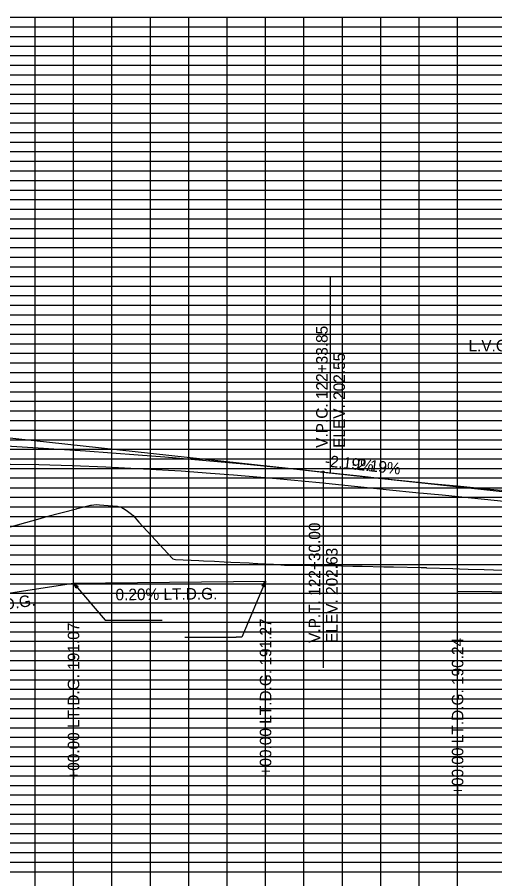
# Model space of a CAD drawing. Extents: x 1451449 to 1456010, y 297581 to 299758.
# Drawn here: x 1453550.4 to 1453799, y 299104.9 to 299553.5 of the extents above; entities that cross this region are included whole.
import ezdxf

# ---------------------------------------------------------------- set-up
doc = ezdxf.new("R2010")
doc.units = 0
for name, color, linetype in [('Existing Profile Grade', 7, 'Continuous'), ('Grid_Major', 7, 'Continuous'), ('Grid_Minor', 7, 'Continuous'), ('PR_Exist Surface', 7, 'Continuous'), ('PR_exist_ground', 7, 'Continuous'), ('PRF_Scratch', 7, 'Continuous'), ('Profile Annotation', 7, 'Continuous'), ('Profile Annotation Line', 7, 'Continuous'), ('Special_Ditch_LT', 7, 'Continuous')]:
    doc.layers.add(name, color=color, linetype=linetype)

msp = doc.modelspace()

# ---------------------------------------------------------------- linework, layer by layer
at = {"layer": 'Existing Profile Grade'}
for points in [[(1453496.53, 299321), (1453514.29, 299320.93), (1453532.09, 299320.86), (1453546.85, 299320.78), (1453561.6, 299320.71), (1453579.05, 299320.08), (1453596.5, 299319.44), (1453616.07, 299318.37), (1453635.64, 299317.31), (1453650.94, 299316.15)], [(1453650.94, 299316.15), (1453663.04, 299315.28)], [(1453663.04, 299315.28), (1453685.36, 299313.25), (1453707.69, 299311.23), (1453725.94, 299309.3), (1453744.18, 299307.37), (1453757.95, 299306.06), (1453771.71, 299304.75), (1453793.64, 299302.54), (1453815.57, 299300.33)]]:
    msp.add_lwpolyline(points, dxfattribs=at)
at = {"layer": 'Grid_Major'}
for p, q in [((1451479.67, 299553.55), (1455979.67, 299553.55)), ((1451479.67, 299553.55), (1455979.67, 299553.55)), ((1453579.67, 298953.55), (1453579.67, 299553.55)), ((1453679.67, 298953.55), (1453679.67, 299553.55)), ((1453779.67, 298953.55), (1453779.67, 299553.55)), ((1451479.67, 299503.55), (1455979.67, 299503.55)), ((1451479.67, 299453.55), (1455979.67, 299453.55)), ((1451479.67, 299403.55), (1455979.67, 299403.55)), ((1451479.67, 299353.55), (1455979.67, 299353.55)), ((1451479.67, 299303.55), (1455979.67, 299303.55)), ((1451479.67, 299253.55), (1455979.67, 299253.55)), ((1451479.67, 299203.55), (1455979.67, 299203.55)), ((1451479.67, 299153.55), (1455979.67, 299153.55))]:
    msp.add_line(p, q, dxfattribs=at)
at = {"layer": 'Grid_Minor'}
for p, q in [((1453559.67, 298953.55), (1453559.67, 299553.55)), ((1453599.67, 298953.55), (1453599.67, 299553.55)), ((1453619.67, 298953.55), (1453619.67, 299553.55)), ((1453639.67, 298953.55), (1453639.67, 299553.55)), ((1453659.67, 298953.55), (1453659.67, 299553.55)), ((1453699.67, 298953.55), (1453699.67, 299553.55)), ((1453719.67, 298953.55), (1453719.67, 299553.55)), ((1453739.67, 298953.55), (1453739.67, 299553.55)), ((1453759.67, 298953.55), (1453759.67, 299553.55)), ((1451479.67, 299548.55), (1455979.67, 299548.55)), ((1451479.67, 299543.55), (1455979.67, 299543.55)), ((1451479.67, 299538.55), (1455979.67, 299538.55)), ((1451479.67, 299533.55), (1455979.67, 299533.55)), ((1451479.67, 299528.55), (1455979.67, 299528.55)), ((1451479.67, 299523.55), (1455979.67, 299523.55)), ((1451479.67, 299518.55), (1455979.67, 299518.55)), ((1451479.67, 299513.55), (1455979.67, 299513.55)), ((1451479.67, 299508.55), (1455979.67, 299508.55)), ((1451479.67, 299498.55), (1455979.67, 299498.55)), ((1451479.67, 299493.55), (1455979.67, 299493.55)), ((1451479.67, 299488.55), (1455979.67, 299488.55)), ((1451479.67, 299483.55), (1455979.67, 299483.55)), ((1451479.67, 299478.55), (1455979.67, 299478.55)), ((1451479.67, 299473.55), (1455979.67, 299473.55)), ((1451479.67, 299468.55), (1455979.67, 299468.55)), ((1451479.67, 299463.55), (1455979.67, 299463.55)), ((1451479.67, 299458.55), (1455979.67, 299458.55)), ((1451479.67, 299448.55), (1455979.67, 299448.55)), ((1451479.67, 299443.55), (1455979.67, 299443.55)), ((1451479.67, 299438.55), (1455979.67, 299438.55)), ((1451479.67, 299433.55), (1455979.67, 299433.55)), ((1451479.67, 299428.55), (1455979.67, 299428.55)), ((1451479.67, 299423.55), (1455979.67, 299423.55)), ((1451479.67, 299418.55), (1455979.67, 299418.55)), ((1451479.67, 299413.55), (1455979.67, 299413.55)), ((1451479.67, 299408.55), (1455979.67, 299408.55)), ((1451479.67, 299398.55), (1455979.67, 299398.55)), ((1451479.67, 299393.55), (1455979.67, 299393.55)), ((1451479.67, 299388.55), (1455979.67, 299388.55)), ((1451479.67, 299383.55), (1455979.67, 299383.55)), ((1451479.67, 299378.55), (1455979.67, 299378.55)), ((1451479.67, 299373.55), (1455979.67, 299373.55)), ((1451479.67, 299368.55), (1455979.67, 299368.55)), ((1451479.67, 299363.55), (1455979.67, 299363.55)), ((1451479.67, 299358.55), (1455979.67, 299358.55)), ((1451479.67, 299348.55), (1455979.67, 299348.55)), ((1451479.67, 299343.55), (1455979.67, 299343.55)), ((1451479.67, 299338.55), (1455979.67, 299338.55)), ((1451479.67, 299333.55), (1455979.67, 299333.55)), ((1451479.67, 299328.55), (1455979.67, 299328.55)), ((1451479.67, 299323.55), (1455979.67, 299323.55)), ((1451479.67, 299318.55), (1455979.67, 299318.55)), ((1451482.2, 299313.64), (1455982.2, 299313.64)), ((1451479.67, 299308.55), (1455979.67, 299308.55)), ((1451479.67, 299298.55), (1455979.67, 299298.55)), ((1451479.67, 299293.55), (1455979.67, 299293.55)), ((1451479.67, 299288.55), (1455979.67, 299288.55)), ((1451479.67, 299283.55), (1455979.67, 299283.55)), ((1451479.67, 299278.55), (1455979.67, 299278.55)), ((1451479.67, 299273.55), (1455979.67, 299273.55)), ((1451479.67, 299268.55), (1455979.67, 299268.55)), ((1451479.67, 299263.55), (1455979.67, 299263.55)), ((1451479.67, 299258.55), (1455979.67, 299258.55)), ((1451479.67, 299248.55), (1455979.67, 299248.55)), ((1451479.67, 299243.55), (1455979.67, 299243.55)), ((1451479.67, 299238.55), (1455979.67, 299238.55)), ((1451479.67, 299233.55), (1455979.67, 299233.55)), ((1451479.67, 299228.55), (1455979.67, 299228.55)), ((1451479.67, 299223.55), (1455979.67, 299223.55)), ((1451479.67, 299218.55), (1455979.67, 299218.55)), ((1451479.67, 299213.55), (1455979.67, 299213.55)), ((1451479.67, 299208.55), (1455979.67, 299208.55)), ((1451479.67, 299198.55), (1455979.67, 299198.55)), ((1451479.67, 299193.55), (1455979.67, 299193.55)), ((1451479.67, 299188.55), (1455979.67, 299188.55)), ((1451479.67, 299183.55), (1455979.67, 299183.55)), ((1451479.67, 299178.55), (1455979.67, 299178.55)), ((1451479.67, 299173.55), (1455979.67, 299173.55)), ((1451479.67, 299168.55), (1455979.67, 299168.55)), ((1451479.67, 299163.55), (1455979.67, 299163.55)), ((1451479.67, 299158.55), (1455979.67, 299158.55)), ((1451479.67, 299148.55), (1455979.67, 299148.55)), ((1451479.67, 299143.55), (1455979.67, 299143.55)), ((1451479.67, 299138.55), (1455979.67, 299138.55)), ((1451479.67, 299133.55), (1455979.67, 299133.55)), ((1451479.67, 299128.55), (1455979.67, 299128.55)), ((1451479.67, 299123.55), (1455979.67, 299123.55)), ((1451479.67, 299118.55), (1455979.67, 299118.55)), ((1451479.67, 299113.55), (1455979.67, 299113.55)), ((1451479.67, 299108.55), (1455979.67, 299108.55))]:
    msp.add_line(p, q, dxfattribs=at)
at = {"layer": 'PR_Exist Surface'}
msp.add_lwpolyline([(1453543.02, 299287.17), (1453562.38, 299292.43), (1453565.04, 299293.36), (1453565.61, 299293.56), (1453581.27, 299297.6), (1453581.55, 299297.71), (1453587.06, 299299.08), (1453588.45, 299299.43), (1453588.96, 299299.46), (1453589.1, 299299.43), (1453591.48, 299299.72), (1453593.12, 299299.59), (1453595.42, 299299.41), (1453602.39, 299298.97), (1453602.93, 299298.8), (1453604.31, 299298.59), (1453607, 299296.89), (1453609.09, 299295.33), (1453610.76, 299294.08), (1453613.62, 299290.54), (1453631.11, 299271.83), (1453631.42, 299271.49), (1453632.86, 299271.15), (1453644.88, 299270.63), (1453647.32, 299270.48), (1453653.13, 299270.22), (1453658.18, 299270), (1453661.61, 299269.78), (1453671.15, 299269.35), (1453675.15, 299269.08), (1453675.68, 299269.04), (1453683.73, 299268.68), (1453689.47, 299268.26), (1453697.17, 299268.23), (1453697.54, 299268.22), (1453707.25, 299268.01), (1453713.66, 299267.97), (1453719.19, 299267.84), (1453725.04, 299267.71), (1453729.94, 299267.67), (1453741.21, 299267.41), (1453742.85, 299267.37), (1453746.37, 299267.34), (1453760.67, 299267), (1453763.23, 299266.91), (1453763.52, 299266.9), (1453777.12, 299266.46), (1453780.72, 299266.34), (1453785.25, 299266.19), (1453793.58, 299265.93), (1453798.3, 299265.77), (1453807.27, 299265.49)], dxfattribs=at)
at = {"layer": 'PR_exist_ground'}
for p, q in [((1453709.67, 299316.72), (1453788.51, 299308.1)), ((1453709.67, 299316.72), (1453788.51, 299308.1)), ((1453709.67, 299316.72), (1453763.51, 299310.83)), ((1453709.67, 299316.72), (1453738.51, 299313.57)), ((1453709.67, 299316.72), (1453713.51, 299316.3)), ((1453599.11, 299239.53), (1453625.86, 299239.53)), ((1453637.64, 299230.76), (1453664.39, 299230.76))]:
    msp.add_line(p, q, dxfattribs=at)
for points in [[(1453544.67, 299330.35), (1453558.42, 299329.55), (1453572.17, 299328.69), (1453585.92, 299327.77), (1453599.67, 299326.78), (1453613.42, 299325.74), (1453627.17, 299324.64), (1453640.92, 299323.47), (1453654.67, 299322.24), (1453668.42, 299320.95), (1453682.17, 299319.6), (1453695.92, 299318.19), (1453709.67, 299316.72)], [(1453544.67, 299330.35), (1453558.42, 299329.55), (1453572.17, 299328.69), (1453585.92, 299327.77), (1453599.67, 299326.78), (1453613.42, 299325.74), (1453627.17, 299324.64), (1453640.92, 299323.47), (1453654.67, 299322.24), (1453668.42, 299320.95), (1453682.17, 299319.6), (1453695.92, 299318.19), (1453709.67, 299316.72)], [(1453544.67, 299330.35), (1453558.42, 299329.55), (1453572.17, 299328.69), (1453585.92, 299327.77), (1453599.67, 299326.78), (1453613.42, 299325.74), (1453627.17, 299324.64), (1453640.92, 299323.47), (1453654.67, 299322.24), (1453668.42, 299320.95), (1453682.17, 299319.6), (1453695.92, 299318.19), (1453709.67, 299316.72)], [(1453544.67, 299330.35), (1453558.42, 299329.55), (1453572.17, 299328.69), (1453585.92, 299327.77), (1453599.67, 299326.78), (1453613.42, 299325.74), (1453627.17, 299324.64), (1453640.92, 299323.47), (1453654.67, 299322.24), (1453668.42, 299320.95), (1453682.17, 299319.6), (1453695.92, 299318.19), (1453709.67, 299316.72)], [(1453544.67, 299330.35), (1453558.42, 299329.55), (1453572.17, 299328.69), (1453585.92, 299327.77), (1453599.67, 299326.78), (1453613.42, 299325.74), (1453627.17, 299324.64), (1453640.92, 299323.47), (1453654.67, 299322.24), (1453668.42, 299320.95), (1453682.17, 299319.6), (1453695.92, 299318.19), (1453709.67, 299316.72)], [(1453713.51, 299316.3), (1453727.05, 299314.83), (1453740.6, 299313.4), (1453754.14, 299312), (1453767.68, 299310.63), (1453781.22, 299309.29), (1453794.76, 299307.98), (1453808.3, 299306.71)], [(1453679.67, 299259.9), (1453667.39, 299230.76), (1453664.39, 299230.76)], [(1453579.67, 299258.9), (1453596.11, 299239.53), (1453599.11, 299239.53)]]:
    msp.add_lwpolyline(points, dxfattribs=at)
for points in [[(1453679.67, 299259.9), (1453679.21, 299256.93), (1453677.87, 299257.5)], [(1453579.67, 299258.9), (1453582.11, 299257.15), (1453581, 299256.21)]]:
    msp.add_lwpolyline(points, close=True, dxfattribs=at)
at = {"layer": 'PRF_Scratch'}
for p, q in [((1453379.67, 299352.79), (1453983.52, 299286.78)), ((1453379.67, 299352.79), (1453983.52, 299286.78)), ((1453379.67, 299352.79), (1453983.52, 299286.78)), ((1453379.67, 299352.79), (1453983.52, 299286.78)), ((1453379.67, 299352.79), (1453983.52, 299286.78)), ((1453379.67, 299352.79), (1453983.52, 299286.78)), ((1453709.67, 299316.72), (1453983.52, 299286.78)), ((1453709.67, 299316.72), (1453853.52, 299300.99)), ((1453709.67, 299316.72), (1453709.67, 299214.72)), ((1453709.67, 299316.72), (1453853.52, 299300.99))]:
    msp.add_line(p, q, dxfattribs=at)
msp.add_lwpolyline([(1453544.67, 299330.35), (1453558.42, 299329.55), (1453572.17, 299328.69), (1453585.92, 299327.77), (1453599.67, 299326.78), (1453613.42, 299325.74), (1453627.17, 299324.64), (1453640.92, 299323.47), (1453654.67, 299322.24), (1453668.42, 299320.95), (1453682.17, 299319.6), (1453695.92, 299318.19), (1453709.67, 299316.72)], dxfattribs=at)
msp.add_lwpolyline([(1453544.67, 299330.35), (1453558.42, 299329.55), (1453572.17, 299328.69), (1453585.92, 299327.77), (1453599.67, 299326.78), (1453613.42, 299325.74), (1453627.17, 299324.64), (1453640.92, 299323.47), (1453654.67, 299322.24), (1453668.42, 299320.95), (1453682.17, 299319.6), (1453695.92, 299318.19), (1453709.67, 299316.72)], dxfattribs=at)
msp.add_lwpolyline([(1453544.67, 299330.35), (1453558.42, 299329.55), (1453572.17, 299328.69), (1453585.92, 299327.77), (1453599.67, 299326.78), (1453613.42, 299325.74), (1453627.17, 299324.64), (1453640.92, 299323.47), (1453654.67, 299322.24), (1453668.42, 299320.95), (1453682.17, 299319.6), (1453695.92, 299318.19), (1453709.67, 299316.72)], dxfattribs=at)
msp.add_circle((1453709.67, 299316.72), 0.5, dxfattribs=at)
msp.add_circle((1453709.67, 299316.72), 0.5, dxfattribs=at)
msp.add_circle((1453709.67, 299316.72), 0.5, dxfattribs=at)
msp.add_circle((1453709.67, 299316.72), 0.5, dxfattribs=at)
at = {"layer": 'Profile Annotation Line'}
for p, q in [((1453713.51, 299316.3), (1453713.51, 299418.3)), ((1453709.67, 299316.72), (1453709.67, 299214.72))]:
    msp.add_line(p, q, dxfattribs=at)
at = {"layer": 'Special_Ditch_LT'}
for points in [[(1453497.08, 299246.1), (1453579.67, 299258.9), (1453679.67, 299259.9)], [(1453779.67, 299254.75), (1453797.48, 299254.5), (1453879.67, 299253.35), (1453979.67, 299251.95), (1454079.67, 299250.55), (1454179.67, 299249.15), (1454279.67, 299247.75), (1454379.67, 299246.35), (1454428.91, 299245.65), (1454479.67, 299244.95), (1454579.67, 299243.9), (1454642.53, 299243.65)]]:
    msp.add_lwpolyline(points, dxfattribs=at)

# ---------------------------------------------------------------- texts
at = {"layer": 'PRF_Scratch'}
for s, rotation, p in [('-2.19%', 353.7613, (1453724.38, 299318.13)), ('V.P.T. 122+30.00', 90, (1453708.17, 299227.72)), ('ELEV. 202.63', 90, (1453717.17, 299227.72))]:
    msp.add_text(s, height=6, rotation=rotation, dxfattribs=at).set_placement(p)
at = {"layer": 'Profile Annotation'}
for s, rotation, p in [('V.P.C. 122+33.85', 90, (1453712.01, 299329.3)), ('ELEV. 202.55', 90, (1453721.01, 299329.3)), ('-2.19%', 353.7613, (1453710.38, 299319.66)), ('V.P.T. 122+30.00', 90, (1453708.17, 299227.72)), ('ELEV. 202.63', 90, (1453717.17, 299227.72)), ('0.20% LT.D.G.', 0.5729, (1453601.57, 299249.88)), ('3.52% LT.D.G.', 8.8098, (1453507.64, 299239.12)), ('+00.00 LT.D.G. 191.07', 90, (1453582.67, 299156.42)), ('+00.00 LT.D.G. 191.27', 90, (1453682.67, 299158.61)), ('+00.00 LT.D.G. 190.24', 90, (1453782.67, 299148.49))]:
    msp.add_text(s, height=6, rotation=rotation, dxfattribs=at).set_placement(p)
msp.add_text("L.V.C. = 650.00'", height=6, dxfattribs=at).set_placement((1453785.34, 299379.54))

doc.saveas('drawing.dxf')
